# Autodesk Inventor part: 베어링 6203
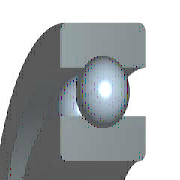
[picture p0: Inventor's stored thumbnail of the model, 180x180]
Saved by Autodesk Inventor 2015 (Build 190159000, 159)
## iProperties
Created: 2012-02
Part Number: 베어링 6203
Material: 강철, 연강
Description: 깊은 그루브 볼 베어링
Document SubType Name: Modeling
Standard: KS B 2023
Designer: mduedu
Standards Organization: KS
Language: ko-KR
Size Designation: 6203 - 17 x 40 x 12
Categories: <MemberInstance><Categories><Category DisplayName="샤프트 부품" InternalName="7f7aeb1f-a693-4053-b835-cee3144e0d98" Mnemonic="SHFT"><Category DisplayName="베어링" Inter
Density: 1 g/cm^3
Appearance: 노란색
IsCustomPart: 1
Author: mduedu
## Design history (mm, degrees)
sketch "스케치" dims "d0" = 5.98 (= -0.26 x WD + 0.26 x BD)
  geometry: L1 (3.01, 14.25)-(8.99, 14.25); L2 (6, 14.25)-(6, 11.26); L3 (6, 14.25)-(6, 17.24); L4 (3.778, 12.249)-(0, 12.249); L5 (0, 8.5)-(12, 8.5); L6 (3.778, 16.251)-(0, 16.251); L7 (0, 20)-(12, 20); L8 (12, 8.5)-(12, 12.249); L9 (8.222, 12.249)-(12, 12.249); L10 (8.222, 16.251)-(12, 16.251); L11 (12, 20)-(12, 16.251); L12 (-1.4, 0)-(8.4, 0) reference; L13 (0, -0.3)-(0, 5.3) reference
  constraints: 22 end point, 4 point on line, 2 collinear, 2 perpendicular, 2 symmetric about line, 1 midpoint, 1 parallel, 14 other
  dimensions: "d9" = 17 diameter of L5 L12 (= WD); "d11" = 40 diameter of L7 L12 (= BD); "d12" = 12 distance between parallel lines of L8 L13 (= KB); "d13" = 24.498 diameter of L9 L12 (= 0.326 x BD + 0.674 x WD)
revolve "본체" stored, may be unused: angle "d6" = 90 deg
revolve "볼" stored, may be unused: angle "d7" = 90 deg
pattern_circular "IDS_ARRAYBALL[SIMPL:T]" dims angle "d3" = 360 deg
body "Solid1"
fillet "모깎기1" dims "d1" = 0.6 (= KRS)
other parameters: "WD" = 17 [user parameter; used in 5 equation terms], "BD" = 40 [user parameter; used in 5 equation terms], "KB" = 12 [user parameter; used in 1 equation term], "KRS" = 0.6 [user parameter; used in 1 equation term], "d4" = 0, "d5" = 0, "d8" = 0, "d14" = 0, "d15" = 0, "BBA" = 0 [user parameter], "BC0" = 4750000 [user parameter], "BC" = 9560000 [user parameter], "WR" = 8.5 (= 0.5 x WD) [user parameter]
